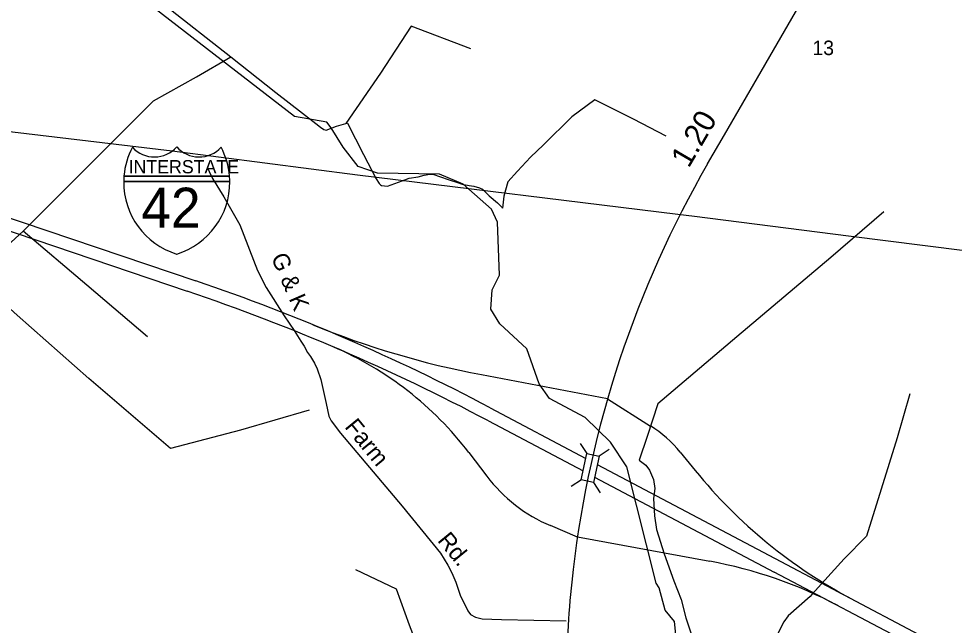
# Model space of a CAD drawing. Extents: x 2315291 to 2336543, y 597177 to 615230.
# Drawn here: x 2325292 to 2330575, y 605840 to 609266 of the extents above; entities that cross this region are included whole.
import ezdxf

# ---------------------------------------------------------------- set-up
doc = ezdxf.new("R2010")
doc.units = 0
for name, color, linetype in [('Exist Hydrographic Creek Single Shore', 7, 'Continuous'), ('Exist Hydrographic Misc Water Feature', 7, 'Continuous'), ('Exist Road Non-System Type 51', 7, 'Continuous'), ('Exist Road Non-System Type 51 Label', 7, 'Continuous'), ('Exist Road Primary US Attributed', 7, 'Continuous'), ('Exist Road Primary US Label', 7, 'Continuous'), ('Exist Road Primary US Mileage Tenths English Label', 7, 'Continuous'), ('Exist Road Primary US Shield CELL', 7, 'Continuous'), ('Exist Road Primary US Shield Number Label', 7, 'Continuous'), ('Exist Road Secondary Structure Standard Bridge CELL', 7, 'Continuous'), ('Exist Utilities Electrical Transmission Line', 7, 'Continuous')]:
    doc.layers.add(name, color=color, linetype=linetype)

msp = doc.modelspace()

# ---------------------------------------------------------------- linework, layer by layer
at = {"layer": 'Exist Hydrographic Creek Single Shore'}
msp.add_lwpolyline([(2329003.3, 605787.4), (2328994.5, 605862.5), (2328943.4, 605926), (2328908.4, 606052.6), (2328891.3, 606078.2), (2328726.5, 606734.4), (2328633.4, 606875.1), (2328490.5, 607013.6), (2328289.3, 607120.4), (2328230.5, 607203.3), (2328161.4, 607400.7), (2328009.4, 607542.3), (2327958.4, 607625.5), (2327966.3, 607734.1), (2328006.3, 607817.7), (2327995.5, 608115.9), (2327961.4, 608190.1), (2327801.3, 608331.2), (2327667.4, 608388.2), (2327317.4, 608393.7), (2327209.3, 608432), (2327124.4, 608540.1), (2327056.3, 608649), (2327031.3, 608680.8), (2326848.4, 608712.7), (2325193.2, 609994.5)], dxfattribs=at)
at = {"layer": 'Exist Hydrographic Misc Water Feature'}
for points in [[(2324978.5, 609588.1), (2325126.6, 609783.6), (2325286.3, 609997.2), (2325664.8, 609705.5), (2326114.7, 609344.5), (2326489.6, 609050.5)], [(2327844.8, 609095.2), (2327507.4, 609223.4), (2327334.4, 608957.8), (2327139.2, 608673.7)], [(2325316.9, 608066.3), (2326052.6, 608801.9), (2326295.2, 608936.6), (2326489.6, 609050.5)], [(2326489.6, 609050.5), (2326743.4, 608849.7), (2326969.8, 608674.1), (2326995.8, 608652.3), (2327015.9, 608640.4), (2327027.6, 608636.6), (2327085.9, 608659), (2327139.2, 608673.7)], [(2328949.2, 608603.3), (2328764.4, 608699.3), (2328545.6, 608806.8), (2328416.2, 608711.5), (2328256.1, 608553.9), (2328182.7, 608483), (2328108, 608404.2), (2328054.1, 608343.8), (2328031.6, 608263.7), (2328024, 608195.4)], [(2327139.2, 608673.7), (2327149.4, 608675.8), (2327239.4, 608498.9), (2327310.4, 608361.6), (2327327, 608336), (2327335, 608327.9), (2327341.1, 608324.2), (2327375, 608320.7), (2327456.8, 608349.3), (2327496.4, 608365.7), (2327548.5, 608372.5), (2327582.1, 608382.8), (2327614.3, 608386.9), (2327636.4, 608385.2), (2327668.4, 608375.5), (2327722.7, 608356.4), (2327770.5, 608340.6), (2327796.6, 608331), (2327834.9, 608323.2), (2327862.8, 608319.9), (2327894.8, 608310.2), (2327911.4, 608302.4), (2327949.3, 608264.7), (2327995.9, 608225.2), (2328019.9, 608201.3), (2328024, 608195.4)], [(2330177.4, 608174.8), (2329878.1, 607917.7), (2329347, 607470), (2328901.6, 607091.3), (2328841.9, 606906.9), (2328796.6, 606772.5)], [(2325045.8, 607803.7), (2325049.9, 607807.6), (2325180.5, 607941.2), (2325316.9, 608066.3)], [(2326019, 607468.3), (2325675.7, 607760.5), (2325316.9, 608066.3)], [(2326932.7, 607054.2), (2326544.3, 606942.4), (2326149.6, 606838), (2325687.4, 607233.1), (2325283.9, 607592.3), (2325045.8, 607803.7)], [(2330324.2, 607146.9), (2330252.7, 606898.2), (2330162.3, 606609.3), (2330079, 606344.4), (2329954.1, 606215.2), (2329770.6, 606013.2), (2329760.6, 606003.4)], [(2328796.6, 606772.5), (2328833.1, 606744.8), (2328853.8, 606715.3), (2328876.2, 606663.2), (2328884.4, 606613.4), (2328877.4, 606555.6), (2328882.3, 606457.5), (2328893, 606381.7), (2328936.5, 606244.2), (2328992.2, 606091.1), (2329033.2, 605985.5), (2329060.3, 605881.7), (2329095.4, 605774.2), (2329136.4, 605680.8), (2329169, 605611), (2329201.8, 605547.7), (2329230.7, 605483.7), (2329243.2, 605464), (2329259.4, 605426.3)], [(2327194.1, 606155.6), (2327423.2, 606046.1), (2327497.4, 605843.1), (2327589.9, 605602.1), (2327728.1, 605607.6), (2327873.9, 605617.3), (2327986, 605410.7), (2328078.1, 605217.6)], [(2329760.6, 606003.4), (2329638.1, 605894), (2329612.5, 605859.8), (2329586.7, 605809.4), (2329549.8, 605731), (2329481.9, 605542.5), (2329436.8, 605458), (2329405.4, 605381.6), (2329348, 605353.4), (2329306.2, 605334.9)]]:
    msp.add_lwpolyline(points, dxfattribs=at)
at = {"layer": 'Exist Road Non-System Type 51'}
msp.add_lwpolyline([(2326359.9, 608419.9), (2326368.2, 608403.2), (2326386.6, 608364), (2326449.9, 608258.9), (2326539.9, 608102.1), (2326640, 607843.6), (2326690, 607748.5), (2326791.7, 607587.5), (2326846.7, 607504.1), (2326885, 607444), (2326903.4, 607415.7), (2326923.4, 607380.6), (2326940, 607359), (2326961.7, 607320.6), (2326976.7, 607288.9), (2326998.4, 607228.8), (2327028.4, 607092.1), (2327043.4, 607022), (2327056.7, 606995.3), (2327108.4, 606925.2), (2327456.8, 606513.2), (2327673, 606246.6), (2327715.2, 606179.9), (2327738.6, 606136.5), (2327760.8, 606084.2), (2327785.3, 606010.3), (2327827.5, 605922.4), (2327844.2, 605900.4), (2327870.8, 605885.7), (2327909.2, 605877.1), (2328019.2, 605873.7), (2328384.3, 605865.4)], dxfattribs=at)
at = {"layer": 'Exist Road Primary US Attributed'}
for p, q in [((2324281.2, 608465.5), (2326291.9, 607784.6)), ((2324248.4, 608402.8), (2326243.3, 607727.1)), ((2327905, 607255.6), (2328617.5, 607120.7)), ((2328617, 607118.9), (2328860.6, 606965.6)), ((2327954.2, 607068.8), (2328494.7, 606782.8)), ((2327944.3, 606994.7), (2328479.4, 606711.6)), ((2327834.2, 606815.2), (2327935.5, 606681.9)), ((2329027.9, 606817.5), (2329112.7, 606713.5)), ((2328559.5, 606748.5), (2329596.5, 606199.9)), ((2328544.3, 606677.3), (2329557.6, 606141.1)), ((2328447.2, 606338.7), (2328294.8, 606403.1)), ((2328447.3, 606339.3), (2329195.1, 606201.6)), ((2329596.5, 606199.9), (2334126.9, 603811.1)), ((2334094.5, 603749.6), (2329557.6, 606141.1))]:
    msp.add_line(p, q, dxfattribs=at)
msp.add_lwpolyline([(2329182.5, 608446.1), (2329277.3, 608610.1), (2329740.8, 609411.6), (2330059.2, 609966.3)], dxfattribs=at)
for centre, radius, start, end in [((2334337.8, 605465.4), 5954.9, 149.9635, 173.35514), ((2322661.9, 597066.3), 11316.3, 62.1165, 71.2898), ((2322528.8, 596759.3), 11579.8, 62.1165, 71.2898), ((2328822.8, 612103.9), 4934.5, 247.7208, 259.2801), ((2326323.3, 605666.6), 1897.9, 37.2438, 66.9257), ((2328493.6, 606382.3), 689.2, 39.1629, 57.8252), ((2328637.9, 607215.9), 882.3, 217.2438, 247.1147), ((2331334.6, 608523.2), 2865.6, 219.1629, 242.221), ((2328736.4, 603709.5), 2534, 62.2048, 79.5707), ((2334337.8, 605465.4), 5954.9, 173.35514, 178.77363)]:
    msp.add_arc(centre, radius, start, end, dxfattribs=at)
at = {"layer": 'Exist Road Primary US Shield CELL'}
for p, q in [((2325886.8, 608377.4), (2325888.3, 608377.4)), ((2326482.3, 608377.4), (2325886.8, 608377.4)), ((2325888.3, 608377.4), (2326482.3, 608377.4)), ((2325888.3, 608377.4), (2326482.3, 608377.4)), ((2325885.3, 608345.9), (2326483.8, 608345.9)), ((2326483.8, 608345.9), (2325885.3, 608345.9)), ((2325885.3, 608345.9), (2326483.8, 608345.9))]:
    msp.add_line(p, q, dxfattribs=at)
for centre, radius, start, end in [((2326308.9, 608341.8), 424.1, 152.1754, 175.1644), ((2326058, 608652.6), 167.7, 222.2998, 318.8506), ((2326310.5, 608652.6), 167.7, 221.1494, 317.7003), ((2326059.6, 608341.8), 424.1, 4.8143, 27.8248), ((2326308.9, 608341.8), 424.1, 175.1857, 179.447), ((2326059.6, 608341.8), 424.1, 0.5526, 4.8127), ((2326308.9, 608341.8), 424.1, 179.4655, 252.7971), ((2326059.6, 608341.8), 424.1, 287.2029, 0.5405)]:
    msp.add_arc(centre, radius, start, end, dxfattribs=at)
at = {"layer": 'Exist Road Secondary Structure Standard Bridge CELL'}
for p, q in [((2328462.9, 606867.3), (2328500.4, 606809.4)), ((2328627.3, 606832.1), (2328569.4, 606794.6)), ((2328469.9, 606661.4), (2328412, 606623.9)), ((2328537.4, 606646.9), (2328574.9, 606589))]:
    msp.add_line(p, q, dxfattribs=at)
msp.add_lwpolyline([(2328569.4, 606794.6), (2328537.7, 606646.8), (2328468.7, 606661.6), (2328500.4, 606809.4)], close=True, dxfattribs=at)
at = {"layer": 'Exist Utilities Electrical Transmission Line'}
for points in [[(2329014.6, 608160.7), (2327204.2, 608382.7), (2326159.3, 608517.4), (2325096.6, 608643.9), (2324570.2, 608706.2), (2322894.9, 608916), (2321924, 609047.6), (2321813.3, 609062.4)], [(2331502, 607839.9), (2330843.2, 607928.1), (2329978.4, 608036.7), (2329107.7, 608149.3), (2329014.6, 608160.7)]]:
    msp.add_lwpolyline(points, dxfattribs=at)

# ---------------------------------------------------------------- texts
at = {"layer": 'Exist Road Non-System Type 51 Label'}
for s, rotation, p in [('G & K', 293.315, (2326715.2, 607918.8)), ('Farm', 309.2762, (2327128.5, 606959.1)), ('Rd.', 309.2762, (2327652.9, 606317.9))]:
    msp.add_text(s, height=95, rotation=rotation, dxfattribs=at).set_placement(p)
at = {"layer": 'Exist Road Primary US Label'}
msp.add_text('13', height=82.02, dxfattribs=at).set_placement((2329774.1, 609060.1))
at = {"layer": 'Exist Road Primary US Mileage Tenths English Label'}
msp.add_text('1.20', height=125, rotation=59.7016, dxfattribs=at).set_placement((2329075.8, 608417.9))
at = {"layer": 'Exist Road Primary US Shield Number Label'}
for s, height, p in [('INTERSTATE', 75, (2325912.3, 608392.4)), ('42', 225, (2325984.3, 608086.4))]:
    msp.add_text(s, height=height, rotation=360, dxfattribs=at).set_placement(p)

doc.saveas('drawing.dxf')
